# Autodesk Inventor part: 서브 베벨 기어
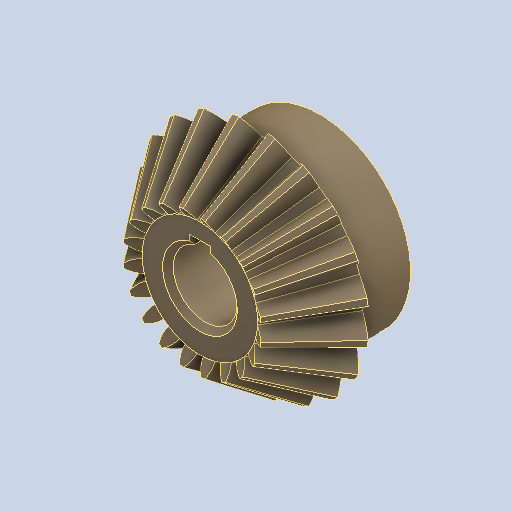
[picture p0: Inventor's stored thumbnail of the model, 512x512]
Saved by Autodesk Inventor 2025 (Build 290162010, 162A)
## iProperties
Created: 2024-07
Part Number: 서브 베벨 기어
Material: 강철, 탄소
Document SubType Name: Modeling
Designer: 학생
Density: 7.87 g/cm^3
Appearance: 기본값
Author: jhkim
Revision Number: 1
Sending System: Autodesk Inventor 2025
Preprocessor: ST-DEVELOPER v20
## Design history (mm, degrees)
node "복구된 형상1"
  node "스케치11"
feature "Solid1"
node "스케치10"
node "솔리드1"
